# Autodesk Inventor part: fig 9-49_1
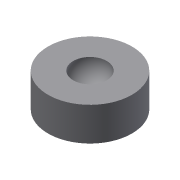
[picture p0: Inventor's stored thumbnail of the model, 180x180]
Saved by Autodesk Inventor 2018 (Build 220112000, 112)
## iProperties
Created: 2013-03
Part Number: fig 9-49_1
Material: Generic
Document SubType Name: Modeling
Designer: CADCIM
Density: 1 g/cm^3
Appearance: Default
Author: CADCIM
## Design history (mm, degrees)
sketch "Sketch1"
  geometry: C1 r 12.5 at (0, 0); 1 further point
  constraints: 1 centre point, 1 coincident
  dimensions: "d0" = 25 diameter of C1
extrude "Extrusion1" new body sketch "Sketch1" distance "d2" = 10; taper "d3" = 0 deg
sketch "Sketch2"
  geometry: L1 (12.5, 10)-(-12.5, 10) reference; L2 (-5, 10)-(5, 10); A1 r 5 centre (0, 10) between (-5, 10) and (5, 10); 1 further point
  constraints: 2 end point, 2 point on circle, 2 point on line, 1 centre point, 1 midpoint
  dimensions: "d4" = 10 diameter of A1
revolve "Revolution1" sketch "Sketch2" stored, may be unused: angle "d6" = 90 deg
body "Solid1"
